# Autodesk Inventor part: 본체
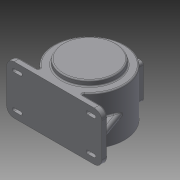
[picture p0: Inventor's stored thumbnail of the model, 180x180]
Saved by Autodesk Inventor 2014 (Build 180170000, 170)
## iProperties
Created: 2015-06
Part Number: 본체
Material: Generic
Document SubType Name: Modeling
Designer: user
Density: 1 g/cm^3
Appearance: Default
Author: user
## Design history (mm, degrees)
sketch "Sketch1"
  geometry: L1 (-115, -59)-(115, -59); L2 (115, -59)-(115, 59); L3 (115, 59)-(-115, 59); L4 (-115, 59)-(-115, -59); L5 (-115, -59)-(115, 59); L6 (115, -59)-(-115, 59); 1 further point
  constraints: 12 end point, 2 midpoint, 2 parallel, 1 horizontal, 1 perpendicular
  dimensions: "d0" = 230 distance of L2.end L3.end; "d1" = 118 distance of L1.end L2.end
extrude "Extrusion1" new body sketch "Sketch1" distance "d2" = 14; taper "d3" = 0 deg
sketch "Sketch2"
  geometry: L1 (115, 59)-(-115, 59) reference; L2 (-97, -41)-(97, -41); L3 (97, -41)-(97, 41); L4 (97, 41)-(-97, 41); L5 (-97, 41)-(-97, -41); L6 (-97, -41)-(97, 41); L7 (97, -41)-(-97, 41); L8 (-97, 41)-(-81, 41); L9 (-97, 37)-(-81, 37); L10 (-81, 45)-(-97, 45); L11 (-97, -41)-(-81, -41); L12 (-97, -37)-(-81, -37); L13 (-81, -45)-(-97, -45); L14 (-81, 32)-(-97, 32); L15 (-97, 50)-(-81, 50); L16 (-81, -32)-(-97, -32); L17 (-97, -50)-(-81, -50); A1 r 4 centre (-97, 41) between (-97, 45) and (-97, 37); A2 r 4 centre (-81, 41) between (-81, 37) and (-81, 45); A3 r 4 centre (-97, -41) between (-97, -37) and (-97, -45); A4 r 4 centre (-81, -41) between (-81, -45) and (-81, -37); A5 r 9 centre (-97, 41) between (-97, 50) and (-97, 32); A6 r 9 centre (-81, 41) between (-81, 32) and (-81, 50); A7 r 9 centre (-97, -41) between (-97, -32) and (-97, -50); A8 r 9 centre (-81, -41) between (-81, -50) and (-81, -32); 5 further points
  constraints: 36 end point, 16 point on circle, 8 centre point, 8 parallel, 8 tangent, 5 midpoint, 1 coincident, 1 horizontal, 1 perpendicular, 6 other
  dimensions: "d4" = 194 distance of L3.end L4.end; "d5" = 82 distance of L2.end L3.end; "d8" = 16 distance of L4.end L8.end; "d9" = 8 distance between parallel lines of L9 L10; "d10" = 16 distance of L11.end L2.start; "d11" = 8 distance between parallel lines of L13 L12; "d12" = 5 distance between parallel lines of L15 L10; "d13" = 5 distance between parallel lines of L16 L12
extrude "Extrusion2" join sketch "Sketch2" distance "d14" = 3; taper "d15" = 0 deg
extrude "Extrusion3" cut sketch "Sketch2" stored distance "d16" = 3; taper "d17" = 0 deg
mirror "Mirror1"
fillet "Fillet1" dims "d18" = 18
fillet "Fillet2" dims "d19" = 3
sketch "Sketch3"
  geometry: L1 (0, 0)-(0, 85); C1 r 85 at (0, 85)
  constraints: 2 end point, 1 centre point, 1 coincident, 1 vertical
  dimensions: "d20" = 85 distance of L1.start L1.end; "d21" = 170 diameter of C1
extrude "Extrusion4" join sketch "Sketch3" stored distance "d22" = 118; taper "d23" = 0 deg
workplane "Work Plane1"
sketch "Sketch4"
  geometry: L1 (97, 0)-(97, 85); C1 r 65 at (97, 85)
  constraints: 2 end point, 1 centre point, 1 coincident, 1 vertical
  dimensions: "d25" = 85 distance of L1.start L1.end; "d26" = 130 diameter of C1
extrude "Extrusion5" join sketch "Sketch4" distance "d27" = 134; taper "d28" = 0 deg
sketch "Sketch5"
  geometry: L1 (0, -85)-(0, 0); C1 r 47.5 at (0, 0)
  constraints: 2 end point, 1 centre point, 1 coincident, 1 vertical
  dimensions: "d29" = 85 distance of L1.start L1.end; "d30" = 95 diameter of C1
extrude "Extrusion6" cut sketch "Sketch5" distance "d31" = 11; taper "d32" = 0 deg
sketch "Sketch6"
  geometry: L1 (0, -85)-(0, 0); C1 r 77 at (0, 0)
  constraints: 2 end point, 1 centre point, 1 coincident, 1 vertical
  dimensions: "d33" = 85 distance of L1.start L1.end; "d34" = 154 diameter of C1
extrude "Extrusion7" cut sketch "Sketch6" distance "d35" = 102; taper "d36" = 0 deg
sketch "Sketch7"
  geometry: L1 (0, -85)-(0, 0); C1 r 77 at (0, 0) reference; C2 r 23.5 at (0, 0)
  constraints: 2 end point, 1 centre point, 1 coincident, 1 vertical
  dimensions: "d37" = 85 distance of L1.start L1.end (derived); "d38" = 47 diameter of C2
extrude "Extrusion8" cut sketch "Sketch7" distance "d39" = 10.5; taper "d40" = 0 deg
sketch "Sketch8"
  geometry: L1 (0, -85)-(0, 0); C1 r 23.5 at (0, 0) reference; C2 r 15 at (0, 0)
  constraints: 2 end point, 1 centre point, 1 coincident, 1 vertical
  dimensions: "d41" = 85 distance of L1.start L1.end (derived); "d42" = 30 diameter of C2
extrude "Extrusion9" cut sketch "Sketch8" distance "d43" = 3; taper "d44" = 0 deg
sketch "Sketch9"
  geometry: L1 (0, -85)-(0, 0); C1 r 23.5 at (0, 0) reference; C2 r 77 at (0, 0) reference; C3 r 31 at (0, 0)
  constraints: 2 end point, 1 centre point, 1 coincident, 1 vertical
  dimensions: "d45" = 85 distance of L1.start L1.end (derived); "d46" = 62 diameter of C3
extrude "Extrusion10" join sketch "Sketch9" distance "d47" = 3.5; taper "d48" = 0 deg
chamfer "Chamfer1" distance "d49" = 3.5; stored, may be unused: second distance "d50" = 2, angle "d51" = 25 deg
sketch "Sketch10"
  geometry: L1 (84.87, 80.297)-(109, 14); L2 (97, 14)-(46.733, 14) reference; L3 (-46.733, 14)-(-97, 14) reference; L4 (109, 14)-(97, 14) reference; L5 (-97, 14)-(-109, 14) reference; L6 (115, 14)-(115, 0) reference; L7 (0, 0)-(115, 0); A1 r 85 centre (0, 85) between (46.733, 14) and (-46.733, 14) reference
  constraints: 4 end point, 1 perpendicular, 1 point on circle, 1 point on line
  dimensions: "d52" = 6 distance from line of L6 L1.end; "d54" = 110 deg angle of L4 L1
feature "Rib1" sketch "Sketch10" dims "d55" = 1, "d56" = 15, "d57" = 0, "d58" = 0, "d59" = 1, "d60" = 1
mirror "Mirror2"
workplane "Work Plane2"
sketch "Sketch11"
  geometry: L1 (42.5, -42.5)-(-42.5, -42.5); L2 (-42.5, -42.5)-(-42.5, 42.5); L3 (-42.5, 42.5)-(42.5, 42.5); L4 (42.5, 42.5)-(42.5, -42.5); L5 (42.5, -42.5)-(-42.5, 42.5); L6 (-42.5, -42.5)-(42.5, 42.5); 1 further point
  constraints: 12 end point, 2 midpoint, 2 parallel, 1 horizontal, 1 perpendicular
  dimensions: "d62" = 85 distance of L2.end L3.end; "d63" = 85 distance of L1.end L2.end
extrude "Extrusion11" join sketch "Sketch11" stored distance "d64" = 3.5; taper "d65" = 0 deg
sketch "Sketch12"
  geometry: C1 r 35 at (0, 0); 1 further point
  constraints: 1 centre point, 1 coincident
  dimensions: "d66" = 70 diameter of C1
extrude "Extrusion12" cut sketch "Sketch12" stored distance "d67" = 3.5; taper "d68" = 0 deg
sketch "Sketch13"
  geometry: L1 (-35.5, -35.5)-(35.5, -35.5); L2 (35.5, -35.5)-(35.5, 35.5); L3 (35.5, 35.5)-(-35.5, 35.5); L4 (-35.5, 35.5)-(-35.5, -35.5); L5 (-35.5, -35.5)-(35.5, 35.5); L6 (35.5, -35.5)-(-35.5, 35.5); C1 r 35 at (0, 0) reference; 4 further points
  constraints: 12 end point, 4 coincident, 2 midpoint, 2 parallel, 1 horizontal, 1 perpendicular
  dimensions: "d69" = 71 distance of L3.end L2.end; "d70" = 71 distance of L2.end L1.end
hole "Hole1" sketch "Sketch13" at (-35.5, 35.5), (35.5, 35.5), (35.5, -35.5), (-35.5, -35.5) diameter "d71" = 3.242; stored, may be unused: countersink angle "d75" = 90 deg, drill point angle "d77" = 118 deg; dims "d72" = 10, "d73" = 4, "d74" = 2, "d76" = 13
sketch "Sketch14" dims "d78" = 110
  geometry: L1 (0, -85)-(0, 0); C1 r 65 at (0, 0) reference; 2 further points
  constraints: 2 end point, 1 coincident, 1 point on line, 1 vertical, 1 vertical alignment, 2 other
hole "Hole2" sketch "Sketch14" at (0, -55) diameter "d79" = 3.242; stored, may be unused: countersink angle "d83" = 90 deg, drill point angle "d85" = 118 deg; dims "d80" = 10, "d81" = 4, "d82" = 2, "d84" = 38
pattern_circular "Circular Pattern1" dims angle "d87" = 360 deg
fillet "Fillet3" dims "d89" = 3
chamfer "Chamfer2" distance "d90" = 1; stored, may be unused: second distance "d91" = 2, angle "d92" = 25 deg
fillet "Fillet4" dims "d93" = 3
chamfer "Chamfer3" distance "d94" = 1; stored, may be unused: second distance "d95" = 2, angle "d96" = 25 deg
fillet "Fillet5" dims "d97" = 7.5
fillet "Fillet6" dims "d98" = 7
fillet "Fillet7" dims "d99" = 3
fillet "Fillet8" dims "d100" = 3
chamfer "Chamfer4" distance "d101" = 1; stored, may be unused: second distance "d102" = 2, angle "d103" = 25 deg
body "Solid1"
other parameters: "d24" = 13, "d61" = -173
